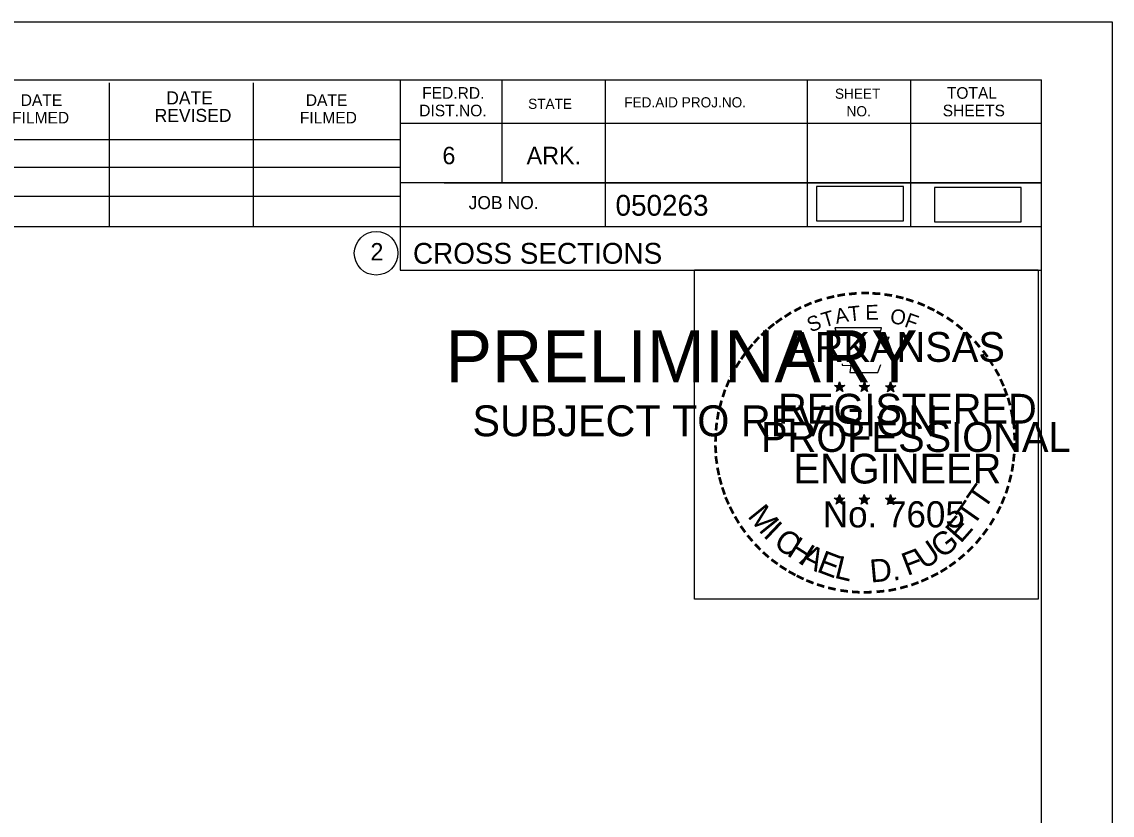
# Model space of a CAD drawing. Extents: x 1365647 to 1367999, y 387113 to 400173.
# Drawn here: x 1365983.7 to 1366057, y 391799.5 to 391852.8 of the extents above; entities that cross this region are included whole.
import ezdxf

# ---------------------------------------------------------------- set-up
doc = ezdxf.new("R2010")
doc.units = 0
for name, color, linetype in [('R_Border', 7, 'Continuous'), ('R_Border PE', 7, 'Continuous'), ('R_Border Prem', 7, 'Continuous'), ('R_Detour', 7, 'Continuous'), ('R_No Plot', 7, 'Continuous')]:
    doc.layers.add(name, color=color, linetype=linetype)

msp = doc.modelspace()

# ---------------------------------------------------------------- linework, layer by layer
at = {"layer": 'R_Border'}
for p, q in [((1365736.095, 391848.937), (1366052.275, 391848.937)), ((1366009.175, 391848.937), (1366009.175, 391836.137)), ((1366016.015, 391848.937), (1366016.015, 391841.997)), ((1366022.955, 391848.937), (1366022.955, 391839.057)), ((1366036.535, 391848.937), (1366036.535, 391839.057)), ((1366043.475, 391848.937), (1366043.475, 391839.057)), ((1366052.275, 391643.477), (1366052.275, 391848.937)), ((1365989.635, 391839.057), (1365989.635, 391848.737)), ((1365999.315, 391839.057), (1365999.315, 391848.737)), ((1366052.275, 391845.997), (1366009.175, 391845.997)), ((1366052.275, 391846.017), (1366052.275, 391846.017)), ((1365970.015, 391844.917), (1366009.175, 391844.917)), ((1365970.015, 391843.057), (1366009.175, 391843.057)), ((1366052.275, 391841.997), (1366009.175, 391841.997)), ((1366012.135, 391841.997), (1366052.275, 391841.997)), ((1365970.015, 391841.117), (1366009.175, 391841.117)), ((1366052.275, 391839.057), (1365970.015, 391839.057)), ((1366009.175, 391836.137), (1366052.275, 391836.137))]:
    msp.add_line(p, q, dxfattribs=at)
msp.add_circle((1366007.562, 391837.272), 1.467, dxfattribs=at)
at = {"layer": 'R_Border PE'}
for p, q in [((1366038.705, 391828.637), (1366038.664, 391828.385)), ((1366038.705, 391828.272), (1366038.705, 391828.637)), ((1366038.705, 391828.637), (1366038.754, 391828.387)), ((1366040.375, 391828.637), (1366040.334, 391828.385)), ((1366040.375, 391828.272), (1366040.375, 391828.637)), ((1366040.375, 391828.637), (1366040.424, 391828.387)), ((1366042.139, 391828.625), (1366042.098, 391828.373)), ((1366042.139, 391828.26), (1366042.139, 391828.625)), ((1366042.139, 391828.625), (1366042.188, 391828.375)), ((1366038.356, 391828.383), (1366038.705, 391828.272)), ((1366038.356, 391828.383), (1366038.609, 391828.338)), ((1366038.356, 391828.383), (1366038.593, 391828.261)), ((1366038.489, 391827.975), (1366038.705, 391828.272)), ((1366038.489, 391827.975), (1366038.615, 391828.219)), ((1366038.489, 391827.975), (1366038.703, 391828.192)), ((1366038.918, 391827.975), (1366038.703, 391828.189)), ((1366039.052, 391828.383), (1366038.705, 391828.272)), ((1366038.918, 391827.975), (1366038.705, 391828.272)), ((1366039.052, 391828.383), (1366038.766, 391828.334)), ((1366038.918, 391827.975), (1366038.781, 391828.266)), ((1366039.052, 391828.383), (1366038.848, 391828.281)), ((1366040.026, 391828.383), (1366040.375, 391828.272)), ((1366040.026, 391828.383), (1366040.279, 391828.338)), ((1366040.026, 391828.383), (1366040.263, 391828.261)), ((1366040.159, 391827.975), (1366040.375, 391828.272)), ((1366040.159, 391827.975), (1366040.285, 391828.219)), ((1366040.159, 391827.975), (1366040.373, 391828.192)), ((1366040.588, 391827.975), (1366040.373, 391828.189)), ((1366040.722, 391828.383), (1366040.375, 391828.272)), ((1366040.588, 391827.975), (1366040.375, 391828.272)), ((1366040.722, 391828.383), (1366040.436, 391828.334)), ((1366040.588, 391827.975), (1366040.451, 391828.266)), ((1366040.722, 391828.383), (1366040.518, 391828.281)), ((1366041.79, 391828.371), (1366042.139, 391828.26)), ((1366041.79, 391828.371), (1366042.043, 391828.326)), ((1366041.79, 391828.371), (1366042.027, 391828.249)), ((1366041.923, 391827.963), (1366042.139, 391828.26)), ((1366041.923, 391827.963), (1366042.049, 391828.207)), ((1366041.923, 391827.963), (1366042.137, 391828.18)), ((1366042.352, 391827.963), (1366042.137, 391828.177)), ((1366042.486, 391828.371), (1366042.139, 391828.26)), ((1366042.352, 391827.963), (1366042.139, 391828.26)), ((1366042.486, 391828.371), (1366042.2, 391828.322)), ((1366042.352, 391827.963), (1366042.215, 391828.254)), ((1366042.486, 391828.371), (1366042.282, 391828.269)), ((1366038.352, 391820.81), (1366038.701, 391820.699)), ((1366038.352, 391820.81), (1366038.605, 391820.765)), ((1366038.352, 391820.81), (1366038.589, 391820.688)), ((1366038.485, 391820.402), (1366038.701, 391820.699)), ((1366038.485, 391820.402), (1366038.611, 391820.646)), ((1366038.485, 391820.402), (1366038.699, 391820.619)), ((1366038.701, 391821.064), (1366038.66, 391820.812)), ((1366038.914, 391820.402), (1366038.699, 391820.616)), ((1366038.701, 391820.699), (1366038.701, 391821.064)), ((1366038.701, 391821.064), (1366038.75, 391820.814)), ((1366039.048, 391820.81), (1366038.701, 391820.699)), ((1366038.914, 391820.402), (1366038.701, 391820.699)), ((1366039.048, 391820.81), (1366038.762, 391820.761)), ((1366038.914, 391820.402), (1366038.777, 391820.693)), ((1366039.048, 391820.81), (1366038.844, 391820.708)), ((1366040.021, 391820.81), (1366040.37, 391820.699)), ((1366040.021, 391820.81), (1366040.274, 391820.765)), ((1366040.021, 391820.81), (1366040.258, 391820.688)), ((1366040.154, 391820.402), (1366040.37, 391820.699)), ((1366040.154, 391820.402), (1366040.28, 391820.646)), ((1366040.154, 391820.402), (1366040.368, 391820.619)), ((1366040.37, 391821.064), (1366040.329, 391820.812)), ((1366040.583, 391820.402), (1366040.368, 391820.616)), ((1366040.37, 391820.699), (1366040.37, 391821.064)), ((1366040.37, 391821.064), (1366040.419, 391820.814)), ((1366040.717, 391820.81), (1366040.37, 391820.699)), ((1366040.583, 391820.402), (1366040.37, 391820.699)), ((1366040.717, 391820.81), (1366040.431, 391820.761)), ((1366040.583, 391820.402), (1366040.446, 391820.693)), ((1366040.717, 391820.81), (1366040.513, 391820.708)), ((1366041.788, 391820.8), (1366042.137, 391820.689)), ((1366041.788, 391820.8), (1366042.041, 391820.755)), ((1366041.788, 391820.8), (1366042.025, 391820.678)), ((1366041.921, 391820.392), (1366042.137, 391820.689)), ((1366041.921, 391820.392), (1366042.047, 391820.636)), ((1366041.921, 391820.392), (1366042.135, 391820.609)), ((1366042.137, 391821.054), (1366042.096, 391820.802)), ((1366042.35, 391820.392), (1366042.135, 391820.606)), ((1366042.137, 391820.689), (1366042.137, 391821.054)), ((1366042.137, 391821.054), (1366042.186, 391820.804)), ((1366042.484, 391820.8), (1366042.137, 391820.689)), ((1366042.35, 391820.392), (1366042.137, 391820.689)), ((1366042.484, 391820.8), (1366042.198, 391820.751)), ((1366042.35, 391820.392), (1366042.213, 391820.683)), ((1366042.484, 391820.8), (1366042.28, 391820.698))]:
    msp.add_line(p, q, dxfattribs=at)
for points in [[(1366038.397, 391832.261), (1366038.666, 391831.434)], [(1366041.908, 391831.339), (1366042.05, 391831.623), (1366041.365, 391831.599), (1366041.513, 391832.261), (1366038.397, 391832.261)], [(1366038.889, 391829.838), (1366038.889, 391829.751), (1366039.452, 391829.732), (1366039.398, 391829.259), (1366041.268, 391829.259), (1366041.469, 391829.795)], [(1366038.705, 391828.637), (1366038.918, 391827.975), (1366038.356, 391828.383), (1366039.052, 391828.383), (1366038.489, 391827.975), (1366038.705, 391828.637)], [(1366040.375, 391828.637), (1366040.588, 391827.975), (1366040.026, 391828.383), (1366040.722, 391828.383), (1366040.159, 391827.975), (1366040.375, 391828.637)], [(1366042.139, 391828.625), (1366042.352, 391827.963), (1366041.79, 391828.371), (1366042.486, 391828.371), (1366041.923, 391827.963), (1366042.139, 391828.625)], [(1366038.701, 391821.064), (1366038.914, 391820.402), (1366038.352, 391820.81), (1366039.048, 391820.81), (1366038.485, 391820.402), (1366038.701, 391821.064)], [(1366040.37, 391821.064), (1366040.583, 391820.402), (1366040.021, 391820.81), (1366040.717, 391820.81), (1366040.154, 391820.402), (1366040.37, 391821.064)], [(1366042.137, 391821.054), (1366042.35, 391820.392), (1366041.788, 391820.8), (1366042.484, 391820.8), (1366041.921, 391820.392), (1366042.137, 391821.054)]]:
    msp.add_lwpolyline(points, dxfattribs=at)
for centre, radius in [((1366038.704, 391828.272), 0.172), ((1366038.704, 391828.272), 0.145), ((1366040.374, 391828.272), 0.172), ((1366040.374, 391828.272), 0.145), ((1366042.138, 391828.26), 0.172), ((1366042.138, 391828.26), 0.145), ((1366038.704, 391828.272), 0.116), ((1366038.704, 391828.272), 0.0991), ((1366038.704, 391828.272), 0.0747), ((1366038.704, 391828.272), 0.0495), ((1366038.704, 391828.272), 0.0296), ((1366040.374, 391828.272), 0.116), ((1366040.374, 391828.272), 0.0991), ((1366040.374, 391828.272), 0.0747), ((1366040.374, 391828.272), 0.0495), ((1366040.374, 391828.272), 0.0296), ((1366042.138, 391828.26), 0.116), ((1366042.138, 391828.26), 0.0991), ((1366042.138, 391828.26), 0.0747), ((1366042.138, 391828.26), 0.0495), ((1366042.138, 391828.26), 0.0296), ((1366038.7, 391820.699), 0.172), ((1366038.7, 391820.699), 0.145), ((1366038.7, 391820.699), 0.116), ((1366038.7, 391820.699), 0.0991), ((1366038.7, 391820.699), 0.0747), ((1366038.7, 391820.699), 0.0495), ((1366038.7, 391820.699), 0.0296), ((1366040.369, 391820.699), 0.172), ((1366040.369, 391820.699), 0.145), ((1366040.369, 391820.699), 0.116), ((1366040.369, 391820.699), 0.0991), ((1366040.369, 391820.699), 0.0747), ((1366040.369, 391820.699), 0.0495), ((1366040.369, 391820.699), 0.0296), ((1366042.136, 391820.689), 0.172), ((1366042.136, 391820.689), 0.145), ((1366042.136, 391820.689), 0.116), ((1366042.136, 391820.689), 0.0991), ((1366042.136, 391820.689), 0.0747), ((1366042.136, 391820.689), 0.0495), ((1366042.136, 391820.689), 0.0296)]:
    msp.add_circle(centre, radius, dxfattribs=at)
at = {"layer": 'R_Detour'}
for points in [[(1366037.165, 391839.457), (1366042.998, 391839.457), (1366042.998, 391841.767), (1366037.165, 391841.767)], [(1366045.079, 391839.387), (1366050.912, 391839.387), (1366050.912, 391841.697), (1366045.079, 391841.697)]]:
    msp.add_lwpolyline(points, close=True, dxfattribs=at)
at = {"layer": 'R_No Plot'}
msp.add_line((1365723.694, 391852.831), (1366057.027, 391852.831), dxfattribs=at)
for points in [[(1365723.687, 391852.831), (1366057.027, 391852.831), (1366057.027, 391639.494), (1365723.687, 391639.494)], [(1366028.946, 391836.169), (1366052.044, 391836.169), (1366052.044, 391814.019), (1366028.946, 391814.019)]]:
    msp.add_lwpolyline(points, close=True, dxfattribs=at)

# ---------------------------------------------------------------- texts
at = {"layer": 'R_Border'}
for s, height, p in [('FED.RD.', 0.7819, (1366010.655, 391847.657)), ('SHEET', 0.684, (1366038.395, 391847.657)), ('TOTAL', 0.7819, (1366045.915, 391847.657)), ('DATE', 0.7819, (1365983.675, 391847.177)), ('DATE', 0.8792, (1365993.455, 391847.277)), ('DATE', 0.7819, (1366002.835, 391847.177)), ('STATE', 0.684, (1366017.775, 391846.977)), ('FED.AID PROJ.NO.', 0.684, (1366024.235, 391847.077)), ('FILMED', 0.7819, (1365983.095, 391845.997)), ('REVISED', 0.8792, (1365992.675, 391846.097)), ('FILMED', 0.7819, (1366002.435, 391845.997)), ('DIST.NO.', 0.7819, (1366010.455, 391846.477)), ('NO.', 0.684, (1366039.175, 391846.477)), ('SHEETS', 0.7819, (1366045.635, 391846.477)), ('6', 1.172, (1366012.015, 391843.257)), ('ARK.', 1.1723, (1366017.675, 391843.257)), ('JOB NO.', 0.8792, (1366013.775, 391840.237)), ('050263', 1.4, (1366023.651, 391839.796)), ('2', 1.172, (1366007.179, 391836.786)), ('CROSS SECTIONS', 1.4, (1366010.038, 391836.567))]:
    msp.add_text(s, height=height, rotation=360, dxfattribs=at).set_placement(p)
at = {"layer": 'R_Border PE'}
for s, height, rotation, p in [('-', 1.6, 13.63015, (1366037.895, 391833.629)), ('-', 1.6, 10.21935, (1366038.573, 391833.791)), ('-', 1.6, 5.89682, (1366039.302, 391833.901)), ('-', 1.6, 0.18623, (1366040.074, 391833.973)), ('-', 1.6, 357.74304, (1366040.797, 391833.96)), ('-', 1.6, 352.16172, (1366041.541, 391833.904)), ('-', 1.6, 347.20489, (1366042.26, 391833.79)), ('-', 1.6, 342.3362, (1366042.895, 391833.635)), ('-', 1.6, 28.79182, (1366035.878, 391832.802)), ('-', 1.6, 24.30721, (1366036.511, 391833.119)), ('-', 1.6, 19.17608, (1366037.145, 391833.388)), ('A', 1, 11.21318, (1366038.492, 391832.521)), ('T', 1, 6.02276, (1366039.341, 391832.687)), ('E', 1, 0.83234, (1366040.446, 391832.797)), ('O', 1, 350.4515, (1366042.05, 391832.587)), ('-', 1.6, 337.85509, (1366043.63, 391833.412)), ('-', 1.6, 334.12109, (1366044.261, 391833.141)), ('-', 1.6, 36.23174, (1366034.703, 391832.037)), ('-', 1.6, 34.06357, (1366035.281, 391832.432)), ('S', 1, 21.59401, (1366036.752, 391831.939)), ('T', 1, 16.4036, (1366037.666, 391832.27)), ('F', 1, 340.07066, (1366043.004, 391832.359)), ('-', 1.6, 329.64089, (1366044.84, 391832.858)), ('-', 1.6, 325.86266, (1366045.483, 391832.497)), ('-', 1.6, 42.96224, (1366033.794, 391831.242)), ('-', 1.6, 38.95066, (1366034.227, 391831.659)), ('-', 1.6, 320.52971, (1366046.093, 391832.071)), ('-', 1.6, 48.42305, (1366033.346, 391830.764)), ('ARKANSAS', 2, 360, (1366035.25, 391829.973)), ('-', 1.6, 315.57859, (1366046.692, 391831.583)), ('-', 1.6, 309.87973, (1366047.261, 391831.033)), ('-', 1.6, 54.23247, (1366032.53, 391829.711)), ('-', 1.6, 50.61417, (1366032.943, 391830.278)), ('-', 1.6, 306.65218, (1366047.786, 391830.431)), ('-', 1.6, 58.07063, (1366032.205, 391829.184)), ('-', 1.4, 303.67529, (1366048.272, 391829.863)), ('-', 1.6, 62.87135, (1366031.892, 391828.57)), ('-', 1.6, 299.66835, (1366048.591, 391829.256)), ('-', 1.6, 67.77427, (1366031.633, 391827.959)), ('-', 1.6, 294.66279, (1366048.915, 391828.644)), ('-', 1.6, 72.39447, (1366031.414, 391827.329)), ('REGISTERED', 2, 360, (1366034.572, 391825.824)), ('DWB', 0.01, 360, (1366038.691, 391828.267)), ('DWB', 0.01, 360, (1366040.361, 391828.267)), ('DWB', 0.01, 360, (1366042.125, 391828.255)), ('-', 1.6, 290.57283, (1366049.172, 391828.067)), ('-', 1.6, 75.46096, (1366031.217, 391826.615)), ('-', 1.6, 285.12326, (1366049.406, 391827.487)), ('-', 1.6, 81.20126, (1366031.085, 391825.902)), ('-', 1.6, 280.54934, (1366049.606, 391826.745)), ('-', 1.6, 85.18634, (1366031.009, 391825.211)), ('PROFESSIONAL', 2, 360, (1366033.424, 391823.92)), ('-', 1.6, 276.59616, (1366049.768, 391825.977)), ('-', 1.6, 89.06224, (1366030.984, 391824.51)), ('-', 1.6, 274.33011, (1366049.828, 391825.255)), ('-', 1.6, 94.19588, (1366031.019, 391823.785)), ('-', 1.6, 269.94067, (1366049.862, 391824.623)), ('-', 1.6, 98.94793, (1366031.091, 391823.118)), ('ENGINEER', 2, 360, (1366035.611, 391821.795)), ('-', 1.6, 263.5172, (1366049.843, 391823.957)), ('-', 1.6, 101.71495, (1366031.226, 391822.385)), ('-', 1.6, 260.99529, (1366049.772, 391823.303)), ('-', 1.6, 105.45785, (1366031.388, 391821.79)), ('T', 1.54, 55.05496, (1366048.42, 391819.964)), ('-', 1.6, 255.7626, (1366049.662, 391822.625)), ('-', 1.6, 109.08742, (1366031.603, 391821.159)), ('-', 1.6, 252.86809, (1366049.481, 391821.905)), ('-', 1.6, 114.06432, (1366031.857, 391820.563)), ('M', 1.54, 308.91747, (1366032.472, 391819.59)), ('No. 7605', 1.757, 360, (1366037.585, 391818.844)), ('DWB', 0.01, 360, (1366038.686, 391820.695)), ('DWB', 0.01, 360, (1366040.355, 391820.693)), ('DWB', 0.01, 360, (1366042.122, 391820.684)), ('T', 1.54, 55.05496, (1366047.689, 391818.844)), ('-', 1.6, 247.88866, (1366049.258, 391821.232)), ('-', 1.6, 115.72885, (1366032.162, 391819.945)), ('-', 1.6, 120.44712, (1366032.519, 391819.359)), ('E', 1.54, 48.73133, (1366046.843, 391817.717)), ('-', 1.6, 244.61971, (1366048.996, 391820.603)), ('-', 1.6, 125.89344, (1366032.922, 391818.798)), ('I', 1.54, 316.46364, (1366033.514, 391818.27)), ('-', 1.6, 239.07125, (1366048.602, 391819.851)), ('-', 1.6, 130.71812, (1366033.384, 391818.246)), ('C', 1.54, 324.01974, (1366034.187, 391817.647)), ('H', 1.54, 327.53419, (1366035.097, 391816.992)), ('G', 1.54, 38.21734, (1366045.59, 391816.697)), ('-', 1.6, 231.25377, (1366047.77, 391818.632)), ('-', 1.6, 233.84524, (1366048.2, 391819.198)), ('-', 1.6, 134.22381, (1366033.901, 391817.701)), ('A', 1.54, 332.55127, (1366035.951, 391816.455)), ('F', 1.54, 20.82016, (1366043.254, 391815.57)), ('U', 1.54, 34.40523, (1366044.391, 391815.964)), ('-', 1.6, 225.76533, (1366047.291, 391818.068)), ('-', 1.6, 138.93382, (1366034.426, 391817.237)), ('-', 1.6, 144.64634, (1366034.982, 391816.831)), ('E', 1.54, 339.20679, (1366037.109, 391815.893)), ('L', 1.54, 346.2929, (1366038.301, 391815.469)), ('D.', 1.54, 5.26016, (1366040.804, 391815.132)), ('-', 1.6, 221.08509, (1366046.769, 391817.559)), ('-', 1.6, 148.08978, (1366035.543, 391816.46)), ('-', 1.6, 151.57039, (1366036.122, 391816.135)), ('-', 1.6, 212.24909, (1366045.686, 391816.7)), ('-', 1.6, 215.73633, (1366046.22, 391817.087)), ('-', 1.6, 154.60019, (1366036.644, 391815.888)), ('-', 1.6, 158.56121, (1366037.268, 391815.634)), ('-', 1.6, 200.71842, (1366043.885, 391815.762)), ('-', 1.6, 204.25161, (1366044.504, 391816.035)), ('-', 1.6, 207.35684, (1366045.128, 391816.354)), ('-', 1.6, 162.79826, (1366037.955, 391815.421)), ('-', 1.6, 167.55551, (1366038.67, 391815.257)), ('-', 1.6, 173.11546, (1366039.442, 391815.147)), ('-', 1.6, 176.51827, (1366040.19, 391815.094)), ('-', 1.6, 181.59176, (1366040.934, 391815.113)), ('-', 1.6, 185.81666, (1366041.743, 391815.189)), ('-', 1.6, 191.28576, (1366042.479, 391815.321)), ('-', 1.6, 195.47429, (1366043.208, 391815.52))]:
    msp.add_text(s, height=height, rotation=rotation, dxfattribs=at).set_placement(p)
at = {"layer": 'R_Border Prem'}
for s, height, p in [('PRELIMINARY', 3.5, (1366012.226, 391828.6)), ('DWB', 0.01, (1366012.973, 391830.449)), ('SUBJECT TO REVISION', 2.07511, (1366014.035, 391824.971))]:
    msp.add_text(s, height=height, rotation=360, dxfattribs=at).set_placement(p)

doc.saveas('drawing.dxf')
